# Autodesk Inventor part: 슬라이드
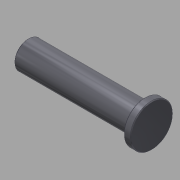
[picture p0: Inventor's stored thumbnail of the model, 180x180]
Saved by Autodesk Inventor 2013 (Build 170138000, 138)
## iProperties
Created: 2015-10
Part Number: 슬라이드
Document SubType Name: Modeling
Designer: mdu
Density: 1 g/cm^3
Material: 강철, 연강
Author: mdu
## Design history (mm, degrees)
sketch "스케치1"
  geometry: L1 (-75, 162)-(-75, 58) reference; L2 (-148, 110)-(22, 110); L3 (-148, 110)-(-148, 129); L4 (-148, 129)-(12, 129); L5 (12, 129)-(12, 139); L6 (12, 139)-(22, 139); L7 (22, 139)-(22, 110); 2 further points
  constraints: 12 end point, 3 parallel, 3 perpendicular, 1 midpoint, 1 point on line
  dimensions: "d0" = 58 diameter of L6 L2; "d1" = 38 diameter of L4 L2; "d2" = 10 distance of L5.end L6.end; "d3" = 170 distance of L2.start L2.end; "d4" = 73 distance between parallel lines of L3 L1
revolve "회전1" sketch "스케치1" stored, may be unused: angle "d5" = 90 deg
hole "구멍1" diameter "d11" = 13.376; stored, may be unused: countersink angle "d15" = 90 deg, drill point angle "d17" = 118 deg; dims "d9" = 10, "d10" = 10, "d12" = 22, "d13" = 4, "d14" = 2, "d16" = 25
chamfer "모따기1" distance "d6" = 1; stored, may be unused: second distance "d7" = 2, angle "d8" = 45 deg
node "솔리드1"
node "참조1"
